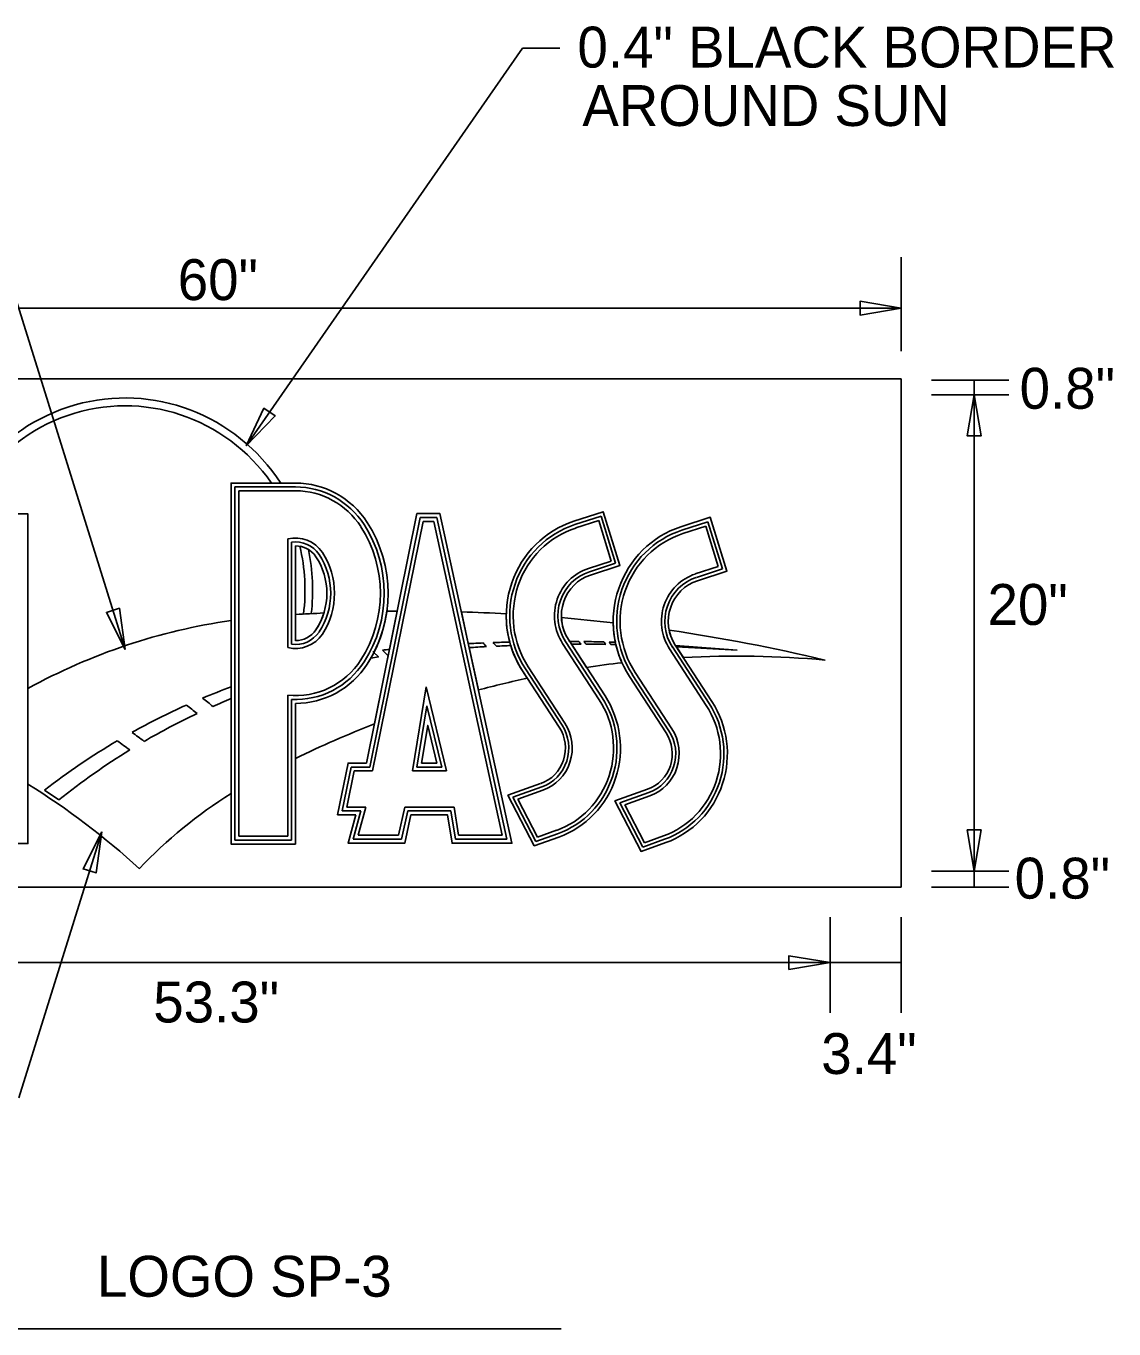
# Model space of a CAD drawing. Extents: x 10268197 to 10268738, y 2141503 to 2142677.
# Drawn here: x 10268635.66 to 10268654.29, y 2142368.15 to 2142390.45 of the extents above; entities that cross this region are included whole.
import ezdxf

# ---------------------------------------------------------------- set-up
doc = ezdxf.new("R2010")
doc.units = 0
for name, color, linetype in [('1', 7, 'Continuous'), ('Default', 7, 'Continuous'), ('GSDims', 7, 'Continuous'), ('TextMisc', 7, 'Continuous')]:
    doc.layers.add(name, color=color, linetype=linetype)

msp = doc.modelspace()

# ---------------------------------------------------------------- linework, layer by layer
at = {"layer": '1'}
for p, q in [((10268639.429, 2142383.264), (10268644.162, 2142390.07)), ((10268644.801, 2142390.07), (10268644.162, 2142390.07)), ((10268637.359, 2142379.776), (10268634.473, 2142389.02)), ((10268641.545, 2142377.766), (10268642.41, 2142382.039)), ((10268642.41, 2142382.039), (10268642.694, 2142382.039)), ((10268642.694, 2142382.039), (10268643.896, 2142376.53)), ((10268641.766, 2142379.767), (10268641.857, 2142379.677)), ((10268642.525, 2142378.816), (10268642.354, 2142377.766)), ((10268642.781, 2142377.766), (10268642.525, 2142378.816)), ((10268642.695, 2142377.834), (10268642.433, 2142377.834)), ((10268641.074, 2142377.014), (10268641.23, 2142377.766)), ((10268641.23, 2142377.766), (10268641.545, 2142377.766)), ((10268642.354, 2142377.766), (10268642.781, 2142377.766)), ((10268640.992, 2142376.947), (10268641.306, 2142376.947)), ((10268641.394, 2142377.014), (10268641.074, 2142377.014)), ((10268641.263, 2142376.53), (10268641.394, 2142377.014)), ((10268642.196, 2142377.014), (10268642.091, 2142376.53)), ((10268642.936, 2142377.014), (10268642.196, 2142377.014)), ((10268643.015, 2142376.53), (10268642.936, 2142377.014)), ((10268636.96, 2142376.66), (10268635.538, 2142372.106)), ((10268642.091, 2142376.53), (10268641.263, 2142376.53)), ((10268643.896, 2142376.53), (10268643.015, 2142376.53)), ((10268650.644, 2142375.711), (10268627.057, 2142375.711))]:
    msp.add_line(p, q, dxfattribs=at)
for points in [[(10268641.306, 2142376.947), (10268641.175, 2142376.463), (10268642.145, 2142376.463), (10268642.25, 2142376.947), (10268642.879, 2142376.947), (10268642.957, 2142376.463), (10268643.98, 2142376.463), (10268642.748, 2142382.106), (10268642.355, 2142382.106), (10268641.49, 2142377.834), (10268641.175, 2142377.834), (10268640.992, 2142376.947)], [(10268641.598, 2142379.745), (10268641.694, 2142379.651), (10268641.565, 2142379.629)], [(10268642.433, 2142377.834), (10268642.538, 2142378.478), (10268642.695, 2142377.834)]]:
    msp.add_lwpolyline(points, dxfattribs=at)
at = {"layer": 'Default'}
for p, q in [((10268639.239, 2142376.514), (10268639.239, 2142382.56)), ((10268639.239, 2142382.56), (10268640.274, 2142382.56)), ((10268639.865, 2142382.627), (10268640.025, 2142382.627)), ((10268639.304, 2142382.493), (10268639.304, 2142376.582)), ((10268640.274, 2142382.493), (10268639.304, 2142382.493)), ((10268639.304, 2142382.493), (10268639.304, 2142376.582)), ((10268640.274, 2142382.493), (10268639.304, 2142382.493)), ((10268642.461, 2142381.972), (10268641.596, 2142377.699)), ((10268642.461, 2142381.972), (10268641.596, 2142377.699)), ((10268642.643, 2142381.972), (10268642.461, 2142381.972)), ((10268642.643, 2142381.972), (10268642.461, 2142381.972)), ((10268643.816, 2142376.598), (10268642.643, 2142381.972)), ((10268643.816, 2142376.598), (10268642.643, 2142381.972)), ((10268645.058, 2142381.916), (10268645.507, 2142382.061)), ((10268645.076, 2142381.858), (10268645.468, 2142381.985)), ((10268645.076, 2142381.858), (10268645.468, 2142381.985)), ((10268645.468, 2142381.985), (10268645.681, 2142381.293)), ((10268645.468, 2142381.985), (10268645.681, 2142381.293)), ((10268645.507, 2142382.061), (10268645.755, 2142381.254)), ((10268646.889, 2142381.82), (10268647.337, 2142381.965)), ((10268646.907, 2142381.763), (10268647.299, 2142381.89)), ((10268646.907, 2142381.763), (10268647.299, 2142381.89)), ((10268647.299, 2142381.89), (10268647.512, 2142381.198)), ((10268647.299, 2142381.89), (10268647.512, 2142381.198)), ((10268647.337, 2142381.965), (10268647.586, 2142381.158)), ((10268640.143, 2142379.811), (10268640.143, 2142381.671)), ((10268640.143, 2142379.811), (10268640.143, 2142381.671)), ((10268640.209, 2142381.615), (10268640.209, 2142379.867)), ((10268640.274, 2142379.929), (10268640.274, 2142381.553)), ((10268645.681, 2142381.293), (10268645.289, 2142381.166)), ((10268645.681, 2142381.293), (10268645.289, 2142381.166)), ((10268645.755, 2142381.254), (10268645.307, 2142381.109)), ((10268647.512, 2142381.198), (10268647.12, 2142381.071)), ((10268647.512, 2142381.198), (10268647.12, 2142381.071)), ((10268647.586, 2142381.158), (10268647.138, 2142381.013)), ((10268640.274, 2142380.377), (10268640.274, 2142379.929)), ((10268641.884, 2142379.781), (10268642.016, 2142380.436)), ((10268643.115, 2142380.422), (10268643.234, 2142379.88)), ((10268639.173, 2142379.138), (10268639.173, 2142380.274)), ((10268640.625, 2142380.115), (10268640.625, 2142380.115)), ((10268644.848, 2142379.883), (10268645.476, 2142378.918)), ((10268644.848, 2142379.883), (10268645.476, 2142378.918)), ((10268644.898, 2142379.916), (10268645.525, 2142378.951)), ((10268645.574, 2142378.985), (10268644.947, 2142379.95)), ((10268644.947, 2142379.95), (10268644.968, 2142379.917)), ((10268644.999, 2142379.869), (10268645.258, 2142379.472)), ((10268647.405, 2142378.889), (10268646.777, 2142379.854)), ((10268646.777, 2142379.854), (10268646.783, 2142379.846)), ((10268646.783, 2142379.846), (10268647.838, 2142379.769)), ((10268641.625, 2142378.504), (10268641.863, 2142379.676)), ((10268643.249, 2142379.811), (10268643.407, 2142379.085)), ((10268646.679, 2142379.787), (10268647.307, 2142378.822)), ((10268646.679, 2142379.787), (10268647.307, 2142378.822)), ((10268646.728, 2142379.821), (10268647.356, 2142378.856)), ((10268647.838, 2142379.769), (10268646.797, 2142379.824)), ((10268646.797, 2142379.824), (10268646.916, 2142379.641)), ((10268641.504, 2142379.528), (10268641.504, 2142379.528)), ((10268644.161, 2142379.413), (10268644.789, 2142378.448)), ((10268644.244, 2142379.286), (10268644.161, 2142379.413)), ((10268644.838, 2142378.482), (10268644.211, 2142379.447)), ((10268644.887, 2142378.515), (10268644.26, 2142379.48)), ((10268644.887, 2142378.515), (10268644.26, 2142379.48)), ((10268645.992, 2142379.318), (10268646.62, 2142378.353)), ((10268646.669, 2142378.386), (10268646.041, 2142379.351)), ((10268646.718, 2142378.42), (10268646.09, 2142379.385)), ((10268646.718, 2142378.42), (10268646.09, 2142379.385)), ((10268635.695, 2142379.111), (10268635.695, 2142377.475)), ((10268640.143, 2142376.582), (10268640.143, 2142378.995)), ((10268640.143, 2142376.582), (10268640.143, 2142378.995)), ((10268642.279, 2142377.699), (10268642.512, 2142379.138)), ((10268642.279, 2142377.699), (10268642.512, 2142379.138)), ((10268642.512, 2142379.138), (10268642.863, 2142377.699)), ((10268642.512, 2142379.138), (10268642.863, 2142377.699)), ((10268639.173, 2142377.315), (10268639.173, 2142378.938)), ((10268640.209, 2142378.923), (10268640.209, 2142376.514)), ((10268640.274, 2142378.854), (10268640.274, 2142377.912)), ((10268641.281, 2142377.699), (10268641.153, 2142377.081)), ((10268641.281, 2142377.699), (10268641.153, 2142377.081)), ((10268641.596, 2142377.699), (10268641.281, 2142377.699)), ((10268641.596, 2142377.699), (10268641.281, 2142377.699)), ((10268642.863, 2142377.699), (10268642.279, 2142377.699)), ((10268642.863, 2142377.699), (10268642.279, 2142377.699)), ((10268643.997, 2142377.248), (10268644.492, 2142377.425)), ((10268636.226, 2142377.206), (10268635.979, 2142377.372)), ((10268644.39, 2142376.492), (10268643.997, 2142377.248)), ((10268644.081, 2142377.214), (10268644.511, 2142377.368)), ((10268644.081, 2142377.214), (10268644.511, 2142377.368)), ((10268644.418, 2142376.567), (10268644.081, 2142377.214)), ((10268644.418, 2142376.567), (10268644.081, 2142377.214)), ((10268645.827, 2142377.153), (10268646.323, 2142377.329)), ((10268645.912, 2142377.119), (10268646.342, 2142377.272)), ((10268645.912, 2142377.119), (10268646.342, 2142377.272)), ((10268641.153, 2142377.081), (10268641.479, 2142377.081)), ((10268641.153, 2142377.081), (10268641.479, 2142377.081)), ((10268641.479, 2142377.081), (10268641.348, 2142376.598)), ((10268641.479, 2142377.081), (10268641.348, 2142376.598)), ((10268642.04, 2142376.598), (10268642.145, 2142377.081)), ((10268642.04, 2142376.598), (10268642.145, 2142377.081)), ((10268642.145, 2142377.081), (10268642.99, 2142377.081)), ((10268642.145, 2142377.081), (10268642.99, 2142377.081)), ((10268642.99, 2142377.081), (10268643.068, 2142376.598)), ((10268642.99, 2142377.081), (10268643.068, 2142376.598)), ((10268646.221, 2142376.397), (10268645.827, 2142377.153)), ((10268646.249, 2142376.471), (10268645.912, 2142377.119)), ((10268646.249, 2142376.471), (10268645.912, 2142377.119)), ((10268640.209, 2142376.514), (10268639.239, 2142376.514)), ((10268639.304, 2142376.582), (10268640.143, 2142376.582)), ((10268639.304, 2142376.582), (10268640.143, 2142376.582)), ((10268641.348, 2142376.598), (10268642.04, 2142376.598)), ((10268641.348, 2142376.598), (10268642.04, 2142376.598)), ((10268643.068, 2142376.598), (10268643.816, 2142376.598)), ((10268643.068, 2142376.598), (10268643.816, 2142376.598)), ((10268644.763, 2142376.625), (10268644.39, 2142376.492)), ((10268644.744, 2142376.683), (10268644.418, 2142376.567)), ((10268644.744, 2142376.683), (10268644.418, 2142376.567)), ((10268646.594, 2142376.53), (10268646.221, 2142376.397)), ((10268646.574, 2142376.587), (10268646.249, 2142376.471)), ((10268646.574, 2142376.587), (10268646.249, 2142376.471)), ((10268650.644, 2142375.711), (10268627.057, 2142375.711)), ((10268634.39, 2142368.148), (10268644.821, 2142368.148))]:
    msp.add_line(p, q, dxfattribs=at)
for points in [[(10268627.057, 2142375.711), (10268627.057, 2142384.409), (10268650.644, 2142384.409), (10268650.644, 2142375.711)], [(10268640.274, 2142382.627), (10268639.173, 2142382.627), (10268639.173, 2142376.447), (10268640.274, 2142376.447), (10268640.274, 2142378.854)], [(10268633.152, 2142376.562), (10268634.122, 2142376.562), (10268634.122, 2142378.873), (10268635.354, 2142376.455), (10268635.695, 2142376.455), (10268635.695, 2142382.098), (10268634.699, 2142382.098), (10268634.699, 2142379.841), (10268633.546, 2142382.205), (10268633.152, 2142382.205)], [(10268645.325, 2142381.051), (10268645.829, 2142381.214), (10268645.545, 2142382.137), (10268645.041, 2142381.973)], [(10268641.449, 2142381.916), (10268641.449, 2142381.916)], [(10268647.155, 2142380.956), (10268647.66, 2142381.119), (10268647.376, 2142382.041), (10268646.871, 2142381.878)], [(10268640.68, 2142381.404), (10268640.679, 2142381.405)], [(10268640.625, 2142380.115), (10268640.625, 2142380.115)], [(10268640.679, 2142380.077), (10268640.68, 2142380.078)], [(10268641.617, 2142379.726), (10268641.694, 2142379.651), (10268641.565, 2142379.629)], [(10268641.863, 2142379.676), (10268641.857, 2142379.677)], [(10268641.449, 2142379.566), (10268641.449, 2142379.566)], [(10268641.504, 2142379.528), (10268641.504, 2142379.528)], [(10268644.472, 2142377.482), (10268643.912, 2142377.282), (10268644.362, 2142376.418), (10268644.782, 2142376.568)], [(10268646.303, 2142377.387), (10268645.743, 2142377.187), (10268646.192, 2142376.323), (10268646.613, 2142376.473)]]:
    msp.add_lwpolyline(points, dxfattribs=at)
for centre, major_axis, ratio, start_param, end_param in [((10268637.358, 2142380.794), (0, 3.29), 0.97582, 5.303349, 7.802858), ((10268637.358, 2142380.794), (0, 3.29), 0.97582, 5.303349, 7.802858), ((10268637.358, 2142380.794), (0, 3.156), 0.97582, 5.332201, 7.884008), ((10268637.358, 2142380.794), (0, 3.156), 0.97582, 5.332201, 7.884008), ((10268640.277, 2142381.118), (0, 1.509), 0.97582, 5.298823, 6.285263), ((10268640.277, 2142381.118), (0, 1.442), 0.97582, 5.29886, 6.285263), ((10268640.274, 2142381.144), (0, 1.35), 0.990269, 5.289759, 6.283185), ((10268640.274, 2142381.144), (0, 1.35), 0.990269, 5.289759, 6.283185), ((10268639.663, 2142380.741), (0, 2.087), 0.989796, 4.135019, 5.289759), ((10268639.663, 2142380.741), (0, 2.087), 0.989796, 4.135019, 5.289759), ((10268640.277, 2142381.118), (0, 1.442), 0.97582, 5.298823, 5.29886), ((10268639.716, 2142380.741), (0, 2.13), 0.97582, 4.127723, 5.297054), ((10268639.716, 2142380.741), (0, 2.13), 0.97582, 5.297054, 5.297084), ((10268639.716, 2142380.741), (0, 2.197), 0.97582, 4.127694, 5.297084), ((10268645.54, 2142380.355), (0, 1.698), 0.97582, 0.306207, 2.15869), ((10268645.54, 2142380.355), (0, 1.637), 0.97582, 0.306207, 2.15869), ((10268645.539, 2142380.355), (0, 1.576), 0.975477, 0.305879, 2.158799), ((10268645.539, 2142380.355), (0, 1.576), 0.975477, 0.305879, 2.158799), ((10268647.371, 2142380.259), (0, 1.698), 0.97582, 0.306207, 2.15869), ((10268640.274, 2142381.144), (0.55, 0), 0.987937, 0.57737, 1.811353), ((10268640.274, 2142381.144), (0.55, 0), 0.987937, 0.57737, 1.811353), ((10268640.278, 2142381.118), (0, 0.501), 0.97582, 5.321397, 6.424928), ((10268647.371, 2142380.259), (0, 1.637), 0.97582, 0.306207, 2.15869), ((10268647.37, 2142380.259), (0, 1.576), 0.975477, 0.305879, 2.158799), ((10268647.37, 2142380.259), (0, 1.576), 0.975477, 0.305879, 2.158799), ((10268640.278, 2142381.118), (0, 0.434), 0.97582, 5.321397, 6.29161), ((10268637.358, 2142380.794), (0, 3.156), 0.97582, 4.58247, 4.952925), ((10268640.274, 2142381.144), (0.419, 0), 0.976302, 1.01124, 1.389925), ((10268637.358, 2142380.794), (0, 3.156), 0.97582, 4.58247, 4.952925), ((10268637.358, 2142380.794), (0, 3.29), 0.97582, 4.590045, 4.925551), ((10268637.358, 2142380.794), (0, 3.29), 0.97582, 4.590045, 4.925551), ((10268639.717, 2142380.741), (0, 1.189), 0.97582, 4.120664, 5.304114), ((10268639.663, 2142380.741), (0, 1.281), 0.998806, 4.135019, 5.289759), ((10268639.663, 2142380.741), (0, 1.281), 0.998806, 4.135019, 5.289759), ((10268639.717, 2142380.741), (0, 1.122), 0.97582, 4.120664, 5.304114), ((10268645.539, 2142380.355), (0, 0.851), 0.975477, 0.305879, 2.158799), ((10268645.539, 2142380.355), (0, 0.851), 0.975477, 0.305879, 2.158799), ((10268645.539, 2142380.355), (0, 0.791), 0.97582, 0.306207, 2.15869), ((10268645.539, 2142380.355), (0, 0.73), 0.97582, 0.306207, 2.15869), ((10268647.37, 2142380.259), (0, 0.851), 0.975477, 0.305879, 2.158799), ((10268647.37, 2142380.259), (0, 0.851), 0.975477, 0.305879, 2.158799), ((10268647.37, 2142380.259), (0, 0.791), 0.97582, 0.306207, 2.15869), ((10268647.37, 2142380.259), (0, 0.73), 0.97582, 0.306207, 2.15869), ((10268642.189, 2142348.859), (0, -31.577), 0.98893, 3.187344, 3.202947), ((10268642.189, 2142348.859), (0, -31.577), 0.98893, 3.187344, 3.202947), ((10268642.189, 2142348.859), (0, -31.577), 0.98893, 3.194251, 3.198517), ((10268639.717, 2142380.741), (0, 1.122), 0.97582, 4.120664, 4.406744), ((10268639.716, 2142380.741), (0, 2.197), 0.97582, 4.232077, 4.572378), ((10268642.189, 2142348.859), (0, -31.577), 0.98893, 3.147118, 3.152801), ((10268642.189, 2142348.859), (0, -31.577), 0.98893, 3.147118, 3.152801), ((10268642.189, 2142348.859), (0, -31.577), 0.98893, 3.087298, 3.111926), ((10268642.189, 2142348.859), (0, -31.577), 0.98893, 3.087298, 3.111926), ((10268645.54, 2142380.355), (0, 1.698), 0.97582, 1.5501, 1.838244), ((10268642.189, 2142348.859), (0, -31.577), 0.98893, 3.028464, 3.056997), ((10268642.189, 2142348.859), (0, -31.577), 0.98893, 3.028464, 3.056997), ((10268645.539, 2142380.355), (0, 0.73), 0.97582, 1.61365, 2.15869), ((10268640.609, 2142369.718), (0, 10.658), 0.97582, 0.138501, 0.492135), ((10268640.609, 2142369.718), (0, 10.658), 0.97582, 0.138501, 0.492135), ((10268640.277, 2142380.365), (0, 0.502), 0.97582, 3.001239, 4.102113), ((10268640.277, 2142380.365), (0, 0.435), 0.97582, 3.134436, 4.102113), ((10268640.277, 2142380.365), (0, 0.435), 0.97582, 3.134436, 4.102113), ((10268647.371, 2142380.259), (0, 1.698), 0.97582, 1.58538, 1.781939), ((10268642.189, 2142348.859), (0, -31.577), 0.98893, 2.910551, 2.997508), ((10268642.189, 2142348.859), (0, -31.577), 0.98893, 2.910551, 2.997508), ((10268647.37, 2142380.259), (0, 0.73), 0.97582, 1.777902, 2.15869), ((10268640.274, 2142380.338), (0.55, 0), 0.987937, 4.471833, 5.705815), ((10268640.274, 2142380.338), (0.55, 0), 0.987937, 4.471833, 5.705815), ((10268644.8, 2142346.677), (0, -33.24), 0.988257, 3.181604, 3.189295), ((10268628.711, 2142366.048), (0, 20.419), 0.984327, 5.453123, 5.457325), ((10268644.8, 2142346.677), (0, -33.24), 0.988257, 3.167715, 3.176345), ((10268628.711, 2142366.048), (0, 20.553), 0.98427, 5.447702, 5.451744), ((10268645.196, 2142346.629), (0, -33.24), 0.988257, 3.179241, 3.186723), ((10268645.54, 2142380.355), (0, 1.698), 0.97582, 1.875041, 2.15869), ((10268644.8, 2142346.677), (0, -33.24), 0.988257, 3.131695, 3.136489), ((10268645.196, 2142346.629), (0, -33.24), 0.988257, 3.142595, 3.147585), ((10268628.711, 2142366.048), (0, 21.695), 0.983807, 5.403078, 5.405838), ((10268644.8, 2142346.677), (0, -33.24), 0.988257, 3.118574, 3.129071), ((10268628.711, 2142366.048), (0, 21.763), 0.983781, 5.400528, 5.403217), ((10268645.196, 2142346.629), (0, -33.24), 0.988257, 3.129621, 3.14), ((10268628.711, 2142366.048), (0, 22.031), 0.98368, 5.390405, 5.392813), ((10268628.711, 2142366.048), (0, 22.098), 0.983655, 5.387892, 5.390232), ((10268644.8, 2142346.677), (0, -33.24), 0.988257, 3.112651, 3.11595), ((10268645.196, 2142346.629), (0, -33.24), 0.988257, 3.124437, 3.127026), ((10268647.371, 2142380.259), (0, 1.698), 0.97582, 1.805305, 2.000126), ((10268639.716, 2142380.741), (0, 2.197), 0.97582, 4.127694, 4.181576), ((10268643.232, 2142367.76), (0, -12.098), 0.987081, 3.2547, 3.264672), ((10268628.711, 2142366.048), (0, 19.076), 0.984951, 5.508238, 5.514999), ((10268645.196, 2142346.629), (0, -33.24), 0.988257, 3.191919, 3.200901), ((10268647.821, 2142361.72), (0, 17.945), 0.975477, 6.196281, 6.334881), ((10268647.821, 2142361.72), (0, 17.945), 0.975477, 6.196281, 6.334881), ((10268640.274, 2142380.338), (0, 1.35), 0.990269, 3.043371, 4.135019), ((10268640.274, 2142380.338), (0, 1.35), 0.990269, 3.043371, 4.135019), ((10268640.277, 2142380.364), (0, 1.442), 0.97582, 3.092812, 4.125918), ((10268640.277, 2142380.364), (0, 1.509), 0.97582, 3.139515, 4.125955), ((10268640.277, 2142380.364), (0, 1.509), 0.97582, 3.139515, 4.125955), ((10268640.277, 2142380.364), (0, 1.442), 0.97582, 4.125918, 4.125955), ((10268639.716, 2142380.741), (0, 2.13), 0.97582, 4.127694, 4.127723), ((10268647.821, 2142361.72), (0, 17.945), 0.975477, 0.111981, 0.146944), ((10268647.821, 2142361.72), (0, 17.945), 0.975477, 0.111981, 0.146944), ((10268647.821, 2142361.72), (0, 17.945), 0.975477, 0.20577, 0.254866), ((10268647.821, 2142361.72), (0, 17.945), 0.975477, 0.20577, 0.254866), ((10268643.232, 2142367.76), (0, -12.098), 0.987081, 3.48834, 3.532255), ((10268628.711, 2142366.048), (0, 16.388), 0.986504, 5.604488, 5.618403), ((10268644.265, 2142378.091), (0, 1.552), 0.97582, 3.476656, 5.300276), ((10268644.265, 2142378.091), (0, 1.612), 0.97582, 3.476656, 5.300276), ((10268643.232, 2142367.76), (0, -12.098), 0.987081, 3.557551, 3.644446), ((10268628.711, 2142366.048), (0, 16.12), 0.986688, 5.613012, 5.627647), ((10268643.627, 2142367.712), (0, -12.098), 0.987081, 3.5238, 3.552221), ((10268644.266, 2142378.091), (0, -1.491), 0.975477, 0.334737, 2.158799), ((10268644.266, 2142378.091), (0, -1.491), 0.975477, 0.334737, 2.158799), ((10268646.097, 2142377.995), (0, -1.491), 0.975477, 0.334737, 2.158799), ((10268646.097, 2142377.995), (0, -1.491), 0.975477, 0.334737, 2.158799), ((10268646.096, 2142377.995), (0, 1.552), 0.97582, 3.476656, 5.300276), ((10268646.096, 2142377.995), (0, 1.612), 0.97582, 3.476656, 5.300276), ((10268643.627, 2142367.712), (0, -12.098), 0.987081, 3.577057, 3.66248), ((10268647.821, 2142361.72), (0, 17.945), 0.975477, 0.36175, 0.445699), ((10268647.821, 2142361.72), (0, 17.945), 0.975477, 0.36175, 0.445699), ((10268644.266, 2142378.091), (0, -0.765), 0.975477, 0.334742, 2.158799), ((10268644.266, 2142378.091), (0, -0.765), 0.975477, 0.334742, 2.158799), ((10268628.711, 2142366.048), (0, 15.179), 0.987382, 5.641271, 5.658477), ((10268644.266, 2142378.091), (0, 0.645), 0.97582, 3.476661, 5.300276), ((10268644.266, 2142378.091), (0, 0.705), 0.97582, 3.476661, 5.300276), ((10268646.096, 2142377.995), (0, 0.645), 0.97582, 3.476661, 5.300276), ((10268646.096, 2142377.995), (0, 0.705), 0.97582, 3.476661, 5.300276), ((10268646.097, 2142377.995), (0, -0.765), 0.975477, 0.334742, 2.158799), ((10268646.097, 2142377.995), (0, -0.765), 0.975477, 0.334742, 2.158799), ((10268643.232, 2142367.76), (0, -12.098), 0.987081, 3.668845, 3.794286), ((10268643.627, 2142367.712), (0, -12.098), 0.987081, 3.686493, 3.810103), ((10268628.711, 2142366.048), (0, 14.911), 0.987597, 5.648885, 5.666846), ((10268628.766, 2142365.835), (0, 13.634), 0.97582, 5.556667, 5.735414), ((10268628.766, 2142365.835), (0, 13.634), 0.97582, 5.556667, 5.735414), ((10268643.325, 2142370.521), (0, -7.986), 0.98893, 3.695067, 3.951695), ((10268643.325, 2142370.521), (0, -7.986), 0.98893, 3.695067, 3.951695)]:
    msp.add_ellipse(centre, major_axis=major_axis, ratio=ratio, start_param=start_param, end_param=end_param, dxfattribs=at)
at = {"layer": 'GSDims'}
for p, q in [((10268627.057, 2142385.621), (10268650.644, 2142385.621)), ((10268651.162, 2142384.391), (10268652.486, 2142384.391)), ((10268651.893, 2142384.137), (10268651.893, 2142384.391)), ((10268651.162, 2142384.137), (10268652.486, 2142384.137)), ((10268651.893, 2142384.137), (10268651.893, 2142375.986)), ((10268651.162, 2142375.986), (10268652.486, 2142375.986)), ((10268651.893, 2142375.711), (10268651.893, 2142375.986)), ((10268651.162, 2142375.711), (10268652.486, 2142375.711)), ((10268649.427, 2142375.197), (10268649.427, 2142373.558)), ((10268650.644, 2142375.197), (10268650.644, 2142373.558)), ((10268628.304, 2142374.419), (10268649.427, 2142374.419)), ((10268649.427, 2142374.419), (10268650.644, 2142374.419))]:
    msp.add_line(p, q, dxfattribs=at)
for points in [[(10268650.644, 2142385.621), (10268649.94, 2142385.503), (10268649.94, 2142385.738)], [(10268651.893, 2142384.137), (10268651.776, 2142383.433), (10268652.011, 2142383.433)], [(10268639.429, 2142383.264), (10268639.928, 2142383.775), (10268639.735, 2142383.909)], [(10268637.359, 2142379.776), (10268637.261, 2142380.483), (10268637.037, 2142380.413)], [(10268636.96, 2142376.66), (10268636.862, 2142375.953), (10268636.638, 2142376.023)], [(10268651.893, 2142375.986), (10268651.776, 2142376.69), (10268652.011, 2142376.69)], [(10268649.427, 2142374.419), (10268648.723, 2142374.536), (10268648.723, 2142374.301)]]:
    msp.add_lwpolyline(points, close=True, dxfattribs=at)
at = {"layer": 'TextMisc'}
msp.add_line((10268650.644, 2142384.887), (10268650.644, 2142386.495), dxfattribs=at)

# ---------------------------------------------------------------- texts
at = {"layer": '1'}
for s, p in [('0.4" BLACK BORDER', (10268645.102, 2142389.739)), ('AROUND SUN', (10268645.186, 2142388.739)), ('60"', (10268638.259, 2142385.759)), ('0.8"', (10268652.672, 2142383.899)), ('20"', (10268652.123, 2142380.199)), ('0.8"', (10268652.587, 2142375.514)), ('53.3"', (10268637.84, 2142373.394)), ('3.4"', (10268649.276, 2142372.512)), ('LOGO SP-3', (10268636.876, 2142368.7))]:
    msp.add_text(s, height=0.7, dxfattribs=at).set_placement(p)

doc.saveas('drawing.dxf')
